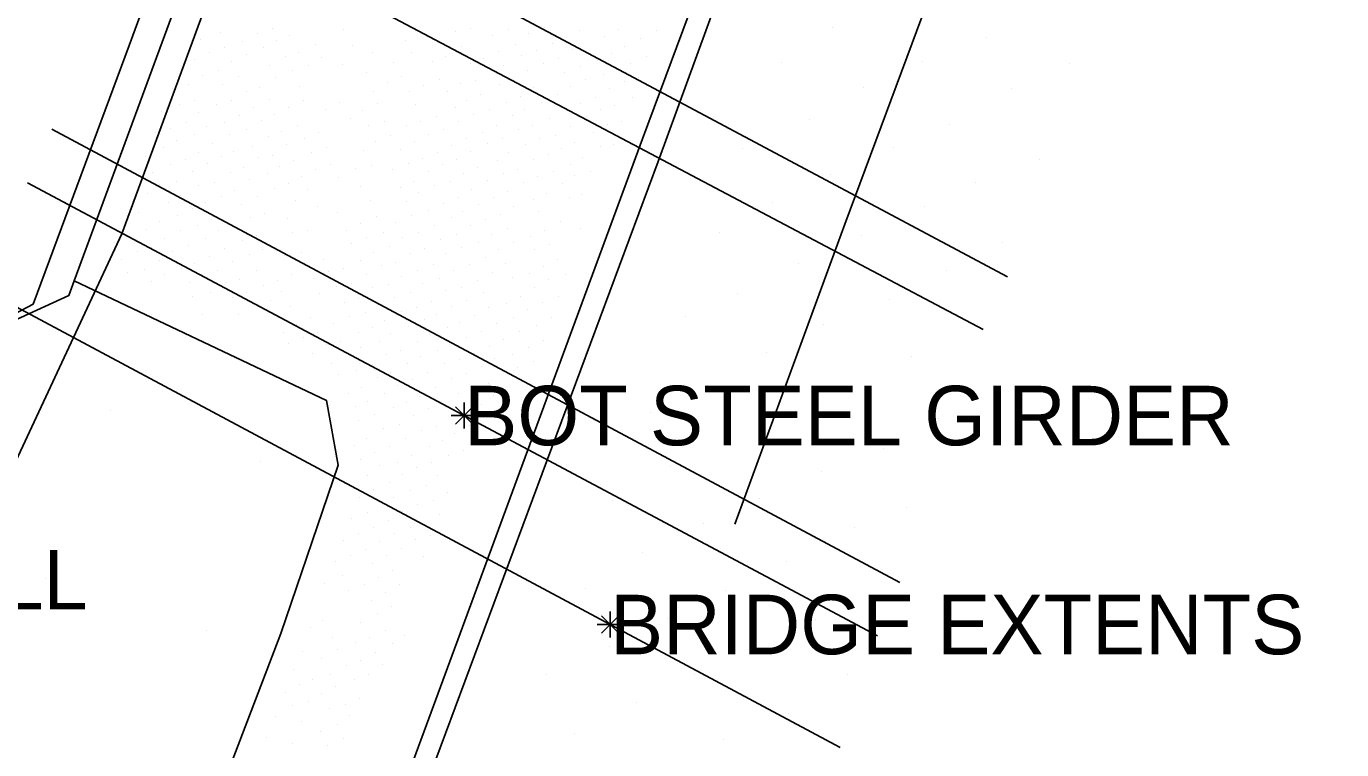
# Model space of a CAD drawing. Extents: x 1729983 to 1730242, y 468641 to 469019.
# Drawn here: x 1730031.77 to 1730071.56, y 468765.72 to 468787.6 of the extents above; entities that cross this region are included whole.
import ezdxf

# ---------------------------------------------------------------- set-up
doc = ezdxf.new("R2010")
doc.units = 0
for name, color, linetype in [('Default', 7, 'Continuous'), ('S_Bridge_Abutment_Bottom', 7, 'Continuous'), ('S_Curb_Type_1', 7, 'Continuous'), ('S_Ground_SpotElevation', 7, 'Continuous'), ('S_Misc_MiscFeature', 7, 'Continuous'), ('S_Misc_MiscItems', 7, 'Continuous'), ('S_Roadway_Edge_Pavement', 7, 'Continuous'), ('S_Roadway_Sidewalks', 7, 'Continuous'), ('S_Text', 7, 'Continuous'), ('S_Utilities_AG_Communications', 7, 'Continuous')]:
    doc.layers.add(name, color=color, linetype=linetype)

# ---------------------------------------------------------------- blocks, each defined once
blk = doc.blocks.new('POINT_DISPLAY')
at = {"layer": 'Default'}
blk.add_line((0, 0), (0, 0), dxfattribs=at)

msp = doc.modelspace()

# ---------------------------------------------------------------- linework, layer by layer
at = {"layer": 'S_Bridge_Abutment_Bottom'}
msp.add_lwpolyline([(1730028.397, 468777.334), (1730030.386, 468778.233), (1730033.055, 468779.454), (1730033.218, 468779.896), (1730038.37, 468793.886), (1730045.609, 468813.805), (1730053.552, 468835.326), (1730061.264, 468856.585), (1730068.104, 468874.933), (1730077.288, 468899.639), (1730081.24, 468910.357), (1730081.674, 468911.604), (1730082.174, 468913.008), (1730079.112, 468916.385)], dxfattribs=at)
at = {"layer": 'S_Curb_Type_1'}
msp.add_lwpolyline([(1730127.344, 469003.745), (1730128.313, 469003.209), (1730129.005, 469001.957), (1730128.001, 468995.343), (1730121.966, 468978.7), (1730114.875, 468959.641), (1730107.952, 468940.794), (1730100.667, 468921.305), (1730089.464, 468890.124), (1730080.18, 468865.229), (1730072.814, 468845.368), (1730066.167, 468827.336), (1730059.271, 468808.011), (1730050.413, 468784.194), (1730032.961, 468736.85), (1730026.597, 468719.521), (1730017.926, 468696.116)], dxfattribs=at)
at = {"layer": 'S_Misc_MiscFeature'}
for p, q in [((1730061.449, 468780.023), (1730035.978, 468793.609)), ((1730060.713, 468778.431), (1730035.235, 468791.904)), ((1730058.193, 468770.778), (1730032.548, 468784.487)), ((1730057.514, 468769.167), (1730031.813, 468782.861)), ((1730029.794, 468780.002), (1730056.391, 468765.781))]:
    msp.add_line(p, q, dxfattribs=at)
for points in [[(1730028.819, 468777.529), (1730031.975, 468779.199), (1730034.887, 468787.021), (1730045.144, 468814.963), (1730055.236, 468842.487), (1730058.712, 468851.879), (1730068.635, 468878.922), (1730072.147, 468888.181), (1730075.727, 468897.903), (1730078.619, 468905.503), (1730081.717, 468913.484), (1730079.668, 468915.827)], [(1730053.2, 468772.537), (1730056.526, 468781.615), (1730059.954, 468790.837), (1730063.295, 468799.884)]]:
    msp.add_lwpolyline(points, dxfattribs=at)
at = {"layer": 'S_Misc_MiscItems'}
for p, q in [((1730045.28, 468775.563), (1730044.756, 468776.087)), ((1730045.28, 468776.087), (1730044.756, 468775.563)), ((1730045.018, 468776.218), (1730045.018, 468775.432)), ((1730045.411, 468775.825), (1730044.625, 468775.825)), ((1730049.82, 468769.505), (1730049.034, 468769.505)), ((1730049.689, 468769.243), (1730049.165, 468769.767)), ((1730049.689, 468769.767), (1730049.165, 468769.243)), ((1730049.427, 468769.898), (1730049.427, 468769.112))]:
    msp.add_line(p, q, dxfattribs=at)
at = {"layer": 'S_Roadway_Edge_Pavement'}
msp.add_lwpolyline([(1730128.624, 468995.344), (1730122.317, 468978.183), (1730114.717, 468957.613), (1730108.465, 468940.563), (1730101.987, 468923.258), (1730100.18, 468918.245), (1730089.85, 468889.621), (1730080.624, 468864.761), (1730073.33, 468845.31), (1730066.507, 468826.616), (1730059.612, 468807.458), (1730050.88, 468783.514), (1730042.113, 468759.912), (1730034.557, 468739.828), (1730031.891, 468732.687), (1730026.743, 468718.512), (1730018.434, 468695.905)], dxfattribs=at)
at = {"layer": 'S_Roadway_Sidewalks'}
msp.add_lwpolyline([(1730033.218, 468779.896), (1730040.852, 468776.278), (1730041.205, 468774.325), (1730039.473, 468769.232), (1730035.785, 468759.578), (1730031.436, 468748.602), (1730024.922, 468730.8), (1730019.096, 468714.972), (1730012.838, 468697.998)], dxfattribs=at)
at = {"layer": 'S_Utilities_AG_Communications'}
msp.add_lwpolyline([(1730120.945, 469004.632), (1730097.184, 468954.408), (1730085.556, 468926.546), (1730082.304, 468910.964), (1730034.658, 468781.323), (1729998.254, 468703.261)], dxfattribs=at)

# ---------------------------------------------------------------- block references
at = {"layer": 'S_Ground_SpotElevation'}
for p in [(1730037.634, 468787.424), (1730039.212, 468787.542), (1730041.376, 468787.497), (1730043.686, 468787.45), (1730044.744, 468787.432), (1730045.196, 468787.535), (1730046.363, 468787.516), (1730047.44, 468787.576), (1730048.492, 468787.47), (1730049.689, 468787.512), (1730050.828, 468787.461), (1730056.163, 468787.567), (1730037.053, 468787.197), (1730038.312, 468787.139), (1730038.759, 468787.395), (1730039.343, 468787.156), (1730039.739, 468787.322), (1730040.529, 468787.058), (1730041.623, 468787.029), (1730043.23, 468787.179), (1730044.267, 468787.143), (1730045.859, 468787.311), (1730046.573, 468787.062), (1730046.947, 468787.37), (1730047.673, 468787.073), (1730049.246, 468787.298), (1730050.354, 468787.223), (1730060.812, 468787.249), (1730037.306, 468786.809), (1730037.766, 468786.951), (1730038.42, 468786.76), (1730038.946, 468786.953), (1730039.615, 468786.683), (1730040.004, 468786.807), (1730040.711, 468786.654), (1730042.232, 468786.809), (1730043.408, 468786.819), (1730044.446, 468786.695), (1730044.943, 468786.982), (1730045.594, 468786.627), (1730046.039, 468786.85), (1730046.735, 468786.714), (1730047.206, 468786.853), (1730047.88, 468786.615), (1730048.301, 468786.89), (1730049.485, 468786.78), (1730049.852, 468786.999), (1730050.528, 468786.682), (1730036.452, 468786.397), (1730036.858, 468786.604), (1730037.576, 468786.275), (1730037.982, 468786.54), (1730039.113, 468786.403), (1730039.812, 468786.269), (1730040.306, 468786.414), (1730041.323, 468786.455), (1730042.888, 468786.504), (1730044.056, 468786.532), (1730045.193, 468786.487), (1730046.214, 468786.401), (1730046.939, 468786.266), (1730047.401, 468786.468), (1730048.541, 468786.377), (1730049.034, 468786.572), (1730050.044, 468786.488), (1730054.626, 468786.515), (1730058.888, 468786.539), (1730063.328, 468786.466), (1730036.67, 468785.837), (1730037.098, 468786.123), (1730037.693, 468785.843), (1730038.195, 468786.078), (1730039.299, 468786.044), (1730042.048, 468786.192), (1730042.685, 468785.908), (1730043.11, 468786.091), (1730044.271, 468786.002), (1730044.903, 468785.884), (1730045.359, 468785.973), (1730046.076, 468785.833), (1730046.454, 468785.969), (1730048.062, 468786.197), (1730048.696, 468785.994), (1730049.227, 468786.132), (1730049.877, 468785.931), (1730050.291, 468786.065), (1730036.195, 468785.728), (1730038.423, 468785.613), (1730038.837, 468785.752), (1730040.038, 468785.768), (1730042.265, 468785.634), (1730043.35, 468785.638), (1730043.788, 468785.815), (1730044.502, 468785.62), (1730045.512, 468785.529), (1730046.729, 468785.471), (1730047.105, 468785.756), (1730047.843, 468785.523), (1730048.242, 468785.782), (1730048.985, 468785.455), (1730049.404, 468785.717), (1730050.092, 468785.441), (1730057.081, 468785.752), (1730061.565, 468785.707), (1730035.871, 468785.023), (1730036.394, 468785.244), (1730036.845, 468785.354), (1730037.518, 468785.241), (1730037.976, 468785.361), (1730038.646, 468785.15), (1730039.134, 468785.388), (1730039.712, 468785.156), (1730040.15, 468785.36), (1730040.826, 468785.094), (1730041.244, 468785.295), (1730041.927, 468785.053), (1730042.392, 468785.27), (1730043.554, 468785.232), (1730044.74, 468785.146), (1730045.097, 468785.364), (1730045.771, 468785.083), (1730046.283, 468785.293), (1730046.852, 468785.072), (1730047.351, 468785.29), (1730048.009, 468785.123), (1730048.521, 468785.261), (1730049.133, 468785.081), (1730049.567, 468785.218), (1730036.618, 468784.704), (1730036.983, 468784.995), (1730037.761, 468784.701), (1730038.232, 468784.906), (1730038.875, 468784.738), (1730039.268, 468784.93), (1730041.57, 468784.799), (1730042.61, 468784.731), (1730043.682, 468784.724), (1730044.184, 468784.882), (1730044.846, 468784.719), (1730045.298, 468784.943), (1730046.47, 468784.892), (1730047.607, 468784.808), (1730048.708, 468784.857), (1730049.365, 468784.627), (1730049.781, 468784.726), (1730055.46, 468784.789), (1730059.693, 468784.642), (1730035.688, 468784.4), (1730036.141, 468784.512), (1730036.85, 468784.341), (1730037.235, 468784.572), (1730037.916, 468784.312), (1730038.43, 468784.473), (1730039.099, 468784.267), (1730039.501, 468784.417), (1730039.97, 468784.612), (1730040.601, 468784.375), (1730042.124, 468784.586), (1730042.788, 468784.297), (1730043.266, 468784.592), (1730043.946, 468784.333), (1730044.399, 468784.49), (1730045.574, 468784.393), (1730045.985, 468784.596), (1730046.673, 468784.464), (1730047.08, 468784.606), (1730047.783, 468784.308), (1730048.238, 468784.578), (1730048.925, 468784.387), (1730035.927, 468783.924), (1730036.301, 468784.146), (1730037.396, 468784.053), (1730038.616, 468783.973), (1730039.645, 468784.015), (1730040.191, 468784.206), (1730040.84, 468783.933), (1730041.957, 468783.829), (1730042.322, 468784.112), (1730043.087, 468783.883), (1730043.524, 468784.129), (1730044.641, 468783.995), (1730045.076, 468784.213), (1730045.731, 468784.069), (1730046.164, 468784.195), (1730046.874, 468784.036), (1730047.292, 468784.196), (1730047.957, 468783.9), (1730048.363, 468784.097), (1730049.144, 468783.952), (1730049.531, 468784.024), (1730053.423, 468783.897), (1730057.993, 468783.948), (1730035.372, 468783.654), (1730036.584, 468783.562), (1730036.99, 468783.786), (1730037.255, 468783.458), (1730037.662, 468783.676), (1730038.052, 468783.825), (1730038.806, 468783.624), (1730039.232, 468783.699), (1730039.866, 468783.537), (1730040.395, 468783.787), (1730043.325, 468783.438), (1730043.76, 468783.61), (1730044.219, 468783.792), (1730044.796, 468783.576), (1730045.22, 468783.821), (1730046.012, 468783.548), (1730046.354, 468783.778), (1730047.099, 468783.575), (1730047.566, 468783.707), (1730048.608, 468783.633), (1730062.407, 468783.584), (1730035.159, 468783.053), (1730035.59, 468783.171), (1730036.141, 468783.409), (1730036.793, 468783.199), (1730037.945, 468783.177), (1730038.352, 468783.329), (1730039.057, 468783.139), (1730039.434, 468783.347), (1730040.084, 468783.058), (1730040.505, 468783.273), (1730040.982, 468783.426), (1730041.719, 468783.305), (1730042.198, 468783.395), (1730042.85, 468783.267), (1730043.932, 468783.209), (1730044.346, 468783.422), (1730044.985, 468783.153), (1730045.418, 468783.342), (1730046.197, 468783.137), (1730046.636, 468783.275), (1730047.222, 468783.068), (1730047.712, 468783.209), (1730048.23, 468783.416), (1730048.357, 468783.091), (1730048.835, 468783.198), (1730056.082, 468783.11), (1730035.805, 468782.8), (1730036.315, 468782.9), (1730036.988, 468782.797), (1730037.469, 468782.869), (1730038.059, 468782.64), (1730038.521, 468782.954), (1730039.269, 468782.688), (1730039.694, 468782.836), (1730040.284, 468782.675), (1730041.226, 468783.027), (1730041.892, 468782.743), (1730043.088, 468782.732), (1730043.471, 468782.904), (1730044.105, 468782.776), (1730044.592, 468782.919), (1730045.252, 468782.653), (1730045.733, 468782.93), (1730046.818, 468782.872), (1730047.995, 468782.859), (1730060.479, 468782.882), (1730034.992, 468782.315), (1730035.435, 468782.534), (1730036.086, 468782.263), (1730036.446, 468782.493), (1730037.179, 468782.257), (1730037.681, 468782.466), (1730038.771, 468782.461), (1730039.907, 468782.339), (1730042.182, 468782.325), (1730043.259, 468782.303), (1730043.639, 468782.558), (1730044.382, 468782.236), (1730044.844, 468782.407), (1730045.913, 468782.418), (1730046.314, 468782.592), (1730047.1, 468782.364), (1730047.511, 468782.545), (1730048.19, 468782.416), (1730048.569, 468782.521), (1730054.339, 468782.267), (1730035.16, 468781.955), (1730036.344, 468781.887), (1730036.786, 468782.075), (1730038.291, 468782.199), (1730038.969, 468781.93), (1730040.581, 468782.155), (1730041.174, 468781.964), (1730042.37, 468781.84), (1730043.426, 468781.862), (1730043.942, 468782.032), (1730044.972, 468782.002), (1730045.447, 468782.195), (1730046.128, 468781.913), (1730046.512, 468782.161), (1730047.257, 468781.993), (1730058.923, 468782.134), (1730035.42, 468781.458), (1730035.804, 468781.68), (1730036.948, 468781.563), (1730037.383, 468781.767), (1730038.064, 468781.534), (1730038.543, 468781.829), (1730039.663, 468781.781), (1730041.887, 468781.637), (1730042.941, 468781.671), (1730044.128, 468781.561), (1730044.621, 468781.814), (1730045.193, 468781.569), (1730045.653, 468781.745), (1730046.315, 468781.487), (1730047.925, 468781.691), (1730048.538, 468781.47), (1730034.448, 468781.049), (1730034.939, 468781.22), (1730035.966, 468781.171), (1730036.433, 468781.436), (1730037.193, 468781.182), (1730037.579, 468781.408), (1730038.317, 468781.134), (1730038.733, 468781.273), (1730039.83, 468781.351), (1730040.281, 468781.43), (1730041.449, 468781.418), (1730042.075, 468781.203), (1730042.571, 468781.363), (1730043.136, 468781.215), (1730043.632, 468781.375), (1730044.286, 468781.143), (1730044.793, 468781.304), (1730045.446, 468781.066), (1730045.857, 468781.301), (1730046.505, 468781.062), (1730047.011, 468781.238), (1730047.43, 468781.41), (1730052.727, 468781.373), (1730057.033, 468781.272), (1730061.307, 468781.061), (1730035.121, 468780.782), (1730035.569, 468780.919), (1730036.201, 468780.784), (1730036.664, 468780.979), (1730037.752, 468780.887), (1730038.526, 468780.687), (1730038.923, 468780.85), (1730039.575, 468780.677), (1730040.083, 468780.772), (1730041.595, 468781.018), (1730042.262, 468780.76), (1730042.748, 468780.926), (1730043.397, 468780.726), (1730043.822, 468780.864), (1730044.45, 468780.713), (1730044.932, 468780.911), (1730046.061, 468780.857), (1730047.138, 468780.839), (1730047.599, 468781.014), (1730034.658, 468780.546), (1730035.35, 468780.248), (1730035.791, 468780.523), (1730036.468, 468780.279), (1730036.861, 468780.435), (1730037.325, 468780.628), (1730038.009, 468780.5), (1730040.753, 468780.532), (1730041.37, 468780.273), (1730041.874, 468780.527), (1730042.512, 468780.362), (1730042.949, 468780.466), (1730044.081, 468780.407), (1730045.19, 468780.395), (1730045.669, 468780.591), (1730046.262, 468780.425), (1730047.406, 468780.332), (1730047.838, 468780.557), (1730055.122, 468780.413), (1730034.836, 468780.146), (1730035.566, 468779.877), (1730035.96, 468780.089), (1730036.719, 468779.854), (1730037.124, 468780.045), (1730037.553, 468780.209), (1730038.222, 468779.936), (1730038.749, 468780.21), (1730039.38, 468779.918), (1730039.795, 468780.106), (1730040.456, 468779.975), (1730040.916, 468780.188), (1730042.069, 468780.097), (1730043.128, 468780.035), (1730043.603, 468780.212), (1730044.262, 468779.962), (1730044.703, 468780.203), (1730045.42, 468779.923), (1730045.869, 468780.156), (1730046.463, 468779.989), (1730046.978, 468780.109), (1730047.568, 468779.946), (1730048.071, 468780.106), (1730059.592, 468780.218), (1730037.344, 468779.533), (1730037.836, 468779.84), (1730038.428, 468779.545), (1730038.947, 468779.768), (1730039.495, 468779.565), (1730040.632, 468779.502), (1730041.151, 468779.732), (1730041.595, 468779.821), (1730042.245, 468779.693), (1730042.736, 468779.789), (1730043.379, 468779.559), (1730043.754, 468779.812), (1730044.451, 468779.605), (1730044.943, 468779.709), (1730045.587, 468779.558), (1730047.157, 468779.695), (1730053.283, 468779.527), (1730036.802, 468779.413), (1730038.02, 468779.393), (1730039.162, 468779.298), (1730039.751, 468779.129), (1730041.408, 468779.23), (1730041.824, 468779.367), (1730042.402, 468779.232), (1730042.899, 468779.398), (1730043.567, 468779.1), (1730044.021, 468779.289), (1730044.627, 468779.111), (1730045.093, 468779.313), (1730045.747, 468779.104), (1730046.305, 468779.229), (1730046.713, 468779.431), (1730047.399, 468779.247), (1730047.878, 468779.427), (1730057.884, 468779.338), (1730037.09, 468778.879), (1730038.184, 468778.875), (1730039.309, 468778.881), (1730040.363, 468778.787), (1730041.558, 468778.827), (1730042.031, 468778.938), (1730042.61, 468778.708), (1730043.117, 468778.973), (1730043.826, 468778.72), (1730044.181, 468778.895), (1730045.326, 468778.839), (1730046.507, 468778.788), (1730046.935, 468779.043), (1730047.655, 468778.778), (1730051.713, 468778.836), (1730039.557, 468778.345), (1730039.954, 468778.579), (1730040.571, 468778.328), (1730041.064, 468778.598), (1730041.807, 468778.35), (1730042.251, 468778.5), (1730042.801, 468778.304), (1730043.335, 468778.515), (1730043.952, 468778.265), (1730044.502, 468778.49), (1730044.863, 468778.631), (1730045.543, 468778.379), (1730045.98, 468778.612), (1730046.69, 468778.366), (1730047.201, 468778.554), (1730055.893, 468778.587), (1730060.529, 468778.573), (1730039.693, 468778.003), (1730040.158, 468778.193), (1730040.845, 468777.964), (1730041.267, 468778.057), (1730041.89, 468777.872), (1730042.462, 468778.066), (1730043.598, 468778.068), (1730044.619, 468778.007), (1730045.082, 468778.187), (1730045.788, 468777.899), (1730046.207, 468778.139), (1730046.946, 468777.887), (1730047.405, 468778.098), (1730040.433, 468777.698), (1730041.573, 468777.695), (1730042.653, 468777.673), (1730043.102, 468777.782), (1730043.692, 468777.6), (1730044.197, 468777.804), (1730044.859, 468777.534), (1730045.314, 468777.717), (1730045.931, 468777.538), (1730046.465, 468777.68), (1730047.126, 468777.474), (1730054.158, 468777.739), (1730058.557, 468777.614), (1730041.013, 468777.411), (1730041.773, 468777.193), (1730042.242, 468777.384), (1730042.8, 468777.122), (1730043.287, 468777.39), (1730043.919, 468777.115), (1730044.406, 468777.39), (1730045.08, 468777.096), (1730045.542, 468777.322), (1730046.638, 468777.28), (1730041.228, 468777.056), (1730041.924, 468776.675), (1730042.404, 468776.965), (1730042.985, 468776.746), (1730043.454, 468776.925), (1730044.16, 468776.682), (1730044.638, 468776.951), (1730045.302, 468776.693), (1730045.739, 468776.803), (1730046.893, 468776.806), (1730052.389, 468776.746), (1730056.734, 468776.68), (1730041.506, 468776.489), (1730042.612, 468776.483), (1730043.677, 468776.412), (1730044.839, 468776.485), (1730045.894, 468776.419), (1730034.311, 468775.979), (1730041.743, 468776.108), (1730042.098, 468776.264), (1730042.863, 468776.083), (1730043.277, 468776.21), (1730043.937, 468776.044), (1730044.287, 468776.203), (1730045.529, 468776.173), (1730050.654, 468775.918), (1730055.034, 468775.986), (1730041.831, 468775.679), (1730042.301, 468775.846), (1730043.061, 468775.548), (1730043.496, 468775.82), (1730044.168, 468775.493), (1730045.178, 468775.517), (1730059.351, 468775.738), (1730042.076, 468775.136), (1730042.589, 468775.421), (1730043.24, 468775.129), (1730043.723, 468775.358), (1730044.73, 468775.276), (1730041.708, 468774.931), (1730042.312, 468774.713), (1730042.747, 468774.898), (1730043.952, 468774.899), (1730044.367, 468775.068), (1730045.003, 468774.781), (1730053.062, 468775.07), (1730057.693, 468774.825), (1730038.859, 468774.432), (1730041.888, 468774.506), (1730042.464, 468774.32), (1730042.992, 468774.402), (1730043.436, 468774.614), (1730044.039, 468774.39), (1730044.538, 468774.609), (1730042.104, 468774.026), (1730043.14, 468774.039), (1730043.566, 468774.245), (1730044.218, 468774.008), (1730051.262, 468774.275), (1730055.816, 468774.144), (1730042.282, 468773.603), (1730042.752, 468773.791), (1730043.383, 468773.564), (1730043.877, 468773.716), (1730044.514, 468773.483), (1730041.862, 468773.35), (1730042.507, 468773.214), (1730042.891, 468773.332), (1730043.603, 468773.123), (1730044.093, 468773.269), (1730049.516, 468773.268), (1730053.951, 468773.31), (1730041.599, 468772.704), (1730042.077, 468772.888), (1730043.146, 468772.934), (1730044.266, 468772.838), (1730058.404, 468773.051), (1730042.27, 468772.452), (1730042.741, 468772.657), (1730043.407, 468772.427), (1730052.245, 468772.556), (1730056.835, 468772.434), (1730041.368, 468772.042), (1730041.815, 468772.246), (1730042.467, 468772.009), (1730042.915, 468772.243), (1730043.556, 468772.073), (1730044.008, 468772.185), (1730041.578, 468771.6), (1730042.038, 468771.78), (1730042.66, 468771.577), (1730043.115, 468771.796), (1730043.775, 468771.563), (1730050.402, 468771.689), (1730041.13, 468771.402), (1730042.229, 468771.358), (1730042.849, 468771.152), (1730054.753, 468771.413), (1730032.368, 468770.886), (1730040.787, 468770.747), (1730041.329, 468770.976), (1730042.011, 468770.703), (1730042.423, 468770.921), (1730043.055, 468770.7), (1730041.53, 468770.543), (1730042.631, 468770.471), (1730048.696, 468770.586), (1730052.912, 468770.526), (1730057.441, 468770.385), (1730042.222, 468770.228), (1730042.81, 468770.06), (1730040.721, 468769.639), (1730041.888, 468769.559), (1730042.387, 468769.846), (1730051.153, 468769.672), (1730055.638, 468769.645), (1730037.217, 468769.326), (1730040.376, 468769.414), (1730041.021, 468769.109), (1730042.649, 468769.328), (1730043.212, 468769.167), (1730041.172, 468768.751), (1730041.715, 468768.974), (1730042.16, 468769.106), (1730042.834, 468768.935), (1730049.422, 468768.839), (1730053.813, 468768.719), (1730040.132, 468768.696), (1730040.706, 468768.478), (1730041.879, 468768.411), (1730042.341, 468768.671), (1730039.858, 468768.131), (1730040.965, 468767.997), (1730041.446, 468768.271), (1730042.109, 468767.997), (1730042.537, 468768.294), (1730047.491, 468767.978), (1730051.977, 468767.983), (1730056.594, 468767.992), (1730040.044, 468767.698), (1730040.442, 468767.849), (1730041.113, 468767.635), (1730041.684, 468767.83), (1730039.598, 468767.45), (1730040.319, 468767.182), (1730040.712, 468767.416), (1730041.835, 468767.279), (1730050.242, 468767.142), (1730039.835, 468767.047), (1730040.946, 468766.961), (1730041.439, 468767.092), (1730041.56, 468766.745), (1730054.816, 468766.822), (1730039.316, 468766.709), (1730040.082, 468766.56), (1730041.191, 468766.483), (1730039.046, 468766.087), (1730040.658, 468766.281), (1730041.364, 468766.045), (1730048.356, 468766.208), (1730052.857, 468766.039), (1730039.821, 468765.913), (1730040.886, 468765.837)]:
    msp.add_blockref('POINT_DISPLAY', p, dxfattribs=at)

# ---------------------------------------------------------------- texts
at = {"layer": 'S_Text'}
for s, p in [('BOT STEEL GIRDER', (1730045.018, 468774.925)), ('BOT WING WALL', (1730014.24, 468769.959)), ('BRIDGE EXTENTS', (1730049.427, 468768.605))]:
    msp.add_text(s, height=1.8, dxfattribs=at).set_placement(p)

doc.saveas('drawing.dxf')
